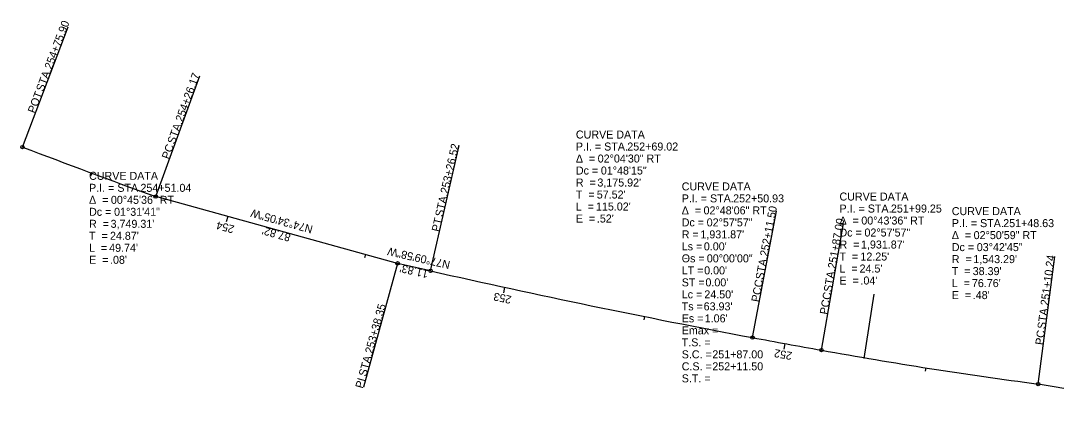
# Model space of a CAD drawing. Extents: x 2479470 to 2480226, y 287083 to 287867.
# Drawn here: x 2479470.1 to 2479832.4, y 287732.9 to 287867.3 of the extents above; entities that cross this region are included whole.
import ezdxf

# ---------------------------------------------------------------- set-up
doc = ezdxf.new("R2010")
doc.units = 0
for name, color, linetype in [('Default', 7, 'Continuous'), ('DV_X_Lot_Line', 7, 'Continuous'), ('DV_X_Property_Line', 7, 'Continuous'), ('GE_X_Alignment_100_Cardinal_Points', 7, 'Continuous'), ('GE_X_Alignment_100_Curve_Data', 7, 'Continuous'), ('GE_X_Alignment_100_Distances', 7, 'Continuous'), ('GE_X_Alignment_100_Stations', 7, 'Continuous')]:
    doc.layers.add(name, color=color, linetype=linetype)

msp = doc.modelspace()

# ---------------------------------------------------------------- linework, layer by layer
at = {"layer": 'Default'}
msp.add_line((2479765.18, 287749.01), (2479768.67, 287771.48), dxfattribs=at)
at = {"layer": 'DV_X_Lot_Line'}
for p, q in [((2479601.94, 287782.3), (2479517.29, 287805.67)), ((2479613.47, 287779.67), (2479601.94, 287782.3)), ((2479867.44, 287732.95), (2479826.02, 287740.04))]:
    msp.add_line(p, q, dxfattribs=at)
for centre, radius, start, end in [((2480801.36, 291328.24), 3749.31, 249.21177, 249.97185), ((2480314.88, 290877.17), 3175.92, 257.24096, 259.31608), ((2480084.24, 289654.69), 1931.87, 259.31608, 260.04266), ((2480026.85, 289270.21), 1543.29, 259.6733, 262.52312)]:
    msp.add_arc(centre, radius, start, end, dxfattribs=at)
at = {"layer": 'GE_X_Alignment_100_Cardinal_Points'}
for p, q in [((2479470.67, 287823.01), (2479486.64, 287865.08)), ((2479517.29, 287805.67), (2479532.7, 287847.95)), ((2479613.47, 287779.67), (2479623.47, 287823.55)), ((2479726.09, 287756.31), (2479734.43, 287800.53)), ((2479750.19, 287751.92), (2479757.97, 287796.24)), ((2479601.94, 287782.3), (2479589.97, 287738.92)), ((2479826.02, 287740.04), (2479831.88, 287784.66))]:
    msp.add_line(p, q, dxfattribs=at)
for centre in [(2479470.67, 287823.01), (2479517.29, 287805.67), (2479601.94, 287782.3), (2479613.47, 287779.67), (2479726.09, 287756.31), (2479750.19, 287751.92), (2479826.02, 287740.04)]:
    msp.add_circle(centre, 0.6, dxfattribs=at)
at = {"layer": 'GE_X_Alignment_100_Stations'}
for p, q in [((2479494.92, 287813.9), (2479494.51, 287812.78)), ((2479542.51, 287798.71), (2479541.98, 287796.78)), ((2479590.71, 287785.4), (2479590.39, 287784.24)), ((2479639.36, 287773.92), (2479638.94, 287771.97)), ((2479688.3, 287763.67), (2479688.06, 287762.5)), ((2479737.4, 287754.21), (2479737.04, 287752.24)), ((2479786.67, 287745.72), (2479786.48, 287744.54))]:
    msp.add_line(p, q, dxfattribs=at)

# ---------------------------------------------------------------- texts
at = {"layer": 'DV_X_Property_Line'}
for s, rotation, p in [('N74°34\'05"W', 164.5682, (2479572.49, 287795.41)), ('N77°09\'58"W', 167.1662, (2479620.5, 287783))]:
    msp.add_text(s, height=2.8, rotation=rotation, dxfattribs=at).set_placement(p)
at = {"layer": 'GE_X_Alignment_100_Cardinal_Points'}
for s, rotation, p in [('254+75.90', 69.2118, (2479480.88, 287850)), (' STA. ', 69.2118, (2479477.57, 287841.28)), ('254+26.17', 69.9719, (2479526.71, 287831.62)), ('POT', 69.2118, (2479475.04, 287834.62)), (' STA. ', 69.9719, (2479523.52, 287822.86)), ('PC', 69.9719, (2479521.94, 287818.54)), ('253+26.52', 77.1662, (2479619.55, 287806.51)), (' STA. ', 77.1662, (2479617.48, 287797.42)), ('252+11.50', 79.3161, (2479731.39, 287784.58)), ('PT', 77.1662, (2479616.51, 287793.18)), ('251+87.00', 80.0427, (2479755.13, 287780.26)), (' STA. ', 79.3161, (2479729.66, 287775.42)), ('251+10.24', 82.5231, (2479829.57, 287767.39)), (' STA. ', 80.0427, (2479753.52, 287771.08)), ('PCC', 79.3161, (2479728.37, 287768.58)), ('PCC', 80.0427, (2479752.32, 287764.22)), ('253+38.35', 74.5682, (2479593.13, 287750.51)), (' STA. ', 82.5231, (2479828.36, 287758.14)), ('PC', 82.5231, (2479827.76, 287753.58)), (' STA. ', 74.5682, (2479590.64, 287741.52)), ('PI', 74.5682, (2479589.76, 287738.32))]:
    msp.add_text(s, height=2.8, rotation=rotation, dxfattribs=at).set_placement(p)
at = {"layer": 'GE_X_Alignment_100_Curve_Data'}
for s, p in [('CURVE DATA', (2479664.29, 287826)), ('P.I. = STA. ', (2479664.29, 287821.8)), ('252+69.02', (2479682.28, 287821.8)), ('Δ  = ', (2479664.29, 287817.6)), ('02°04\'30" RT', (2479671.93, 287817.6)), ('CURVE DATA', (2479493.98, 287811.54)), ('Dc = ', (2479664.29, 287813.4)), ('01°48\'15"', (2479673.03, 287813.4)), ('R  = ', (2479664.29, 287809.2)), ("3,175.92'", (2479671.82, 287809.2)), ('CURVE DATA', (2479701.32, 287807.84)), ('P.I. = STA. ', (2479493.98, 287807.34)), ('254+51.04', (2479511.97, 287807.34)), ('T  = ', (2479664.29, 287805)), ("57.52'", (2479671.61, 287805)), ('CURVE DATA', (2479756.51, 287804.29)), ('Δ  = ', (2479493.98, 287803.14)), ('00°45\'36" RT', (2479501.63, 287803.14)), ('L  = ', (2479664.29, 287800.8)), ("115.02'", (2479671.32, 287800.8)), ('P.I. = STA. ', (2479701.32, 287803.64)), ('252+50.93', (2479719.31, 287803.64)), ('Dc = ', (2479493.98, 287798.94)), ('01°31\'41"', (2479502.73, 287798.94)), ('Δ  = ', (2479701.32, 287799.44)), ('02°48\'06" RT', (2479708.96, 287799.44)), ('P.I. = STA. ', (2479756.51, 287800.09)), ('251+99.25', (2479774.5, 287800.09)), ('CURVE DATA', (2479795.8, 287799.18)), ('R  = ', (2479493.98, 287794.74)), ("3,749.31'", (2479501.52, 287794.74)), ('E  = ', (2479664.29, 287796.6)), (".52'", (2479671.63, 287796.6)), ('Dc = ', (2479701.32, 287795.24)), ('02°57\'57"', (2479710.06, 287795.24)), ('Δ  = ', (2479756.51, 287795.89)), ('00°43\'36" RT', (2479764.15, 287795.89)), ('P.I. = STA. ', (2479795.8, 287794.98)), ('251+48.63', (2479813.79, 287794.98)), ('T  = ', (2479493.98, 287790.54)), ("24.87'", (2479501.3, 287790.54)), ('R = ', (2479701.32, 287791.04)), ("1,931.87'", (2479707.86, 287791.04)), ('Dc = ', (2479756.51, 287791.69)), ('02°57\'57"', (2479765.25, 287791.69)), ('Δ  = ', (2479795.8, 287790.78)), ('02°50\'59" RT', (2479803.45, 287790.78)), ('L  = ', (2479493.98, 287786.34)), ("49.74'", (2479501.02, 287786.34)), ('Ls = ', (2479701.32, 287786.84)), ("0.00'", (2479709.06, 287786.84)), ('R  = ', (2479756.51, 287787.49)), ("1,931.87'", (2479764.04, 287787.49)), ('Dc = ', (2479795.8, 287786.58)), ('03°42\'45"', (2479804.54, 287786.58)), ('Θs = ', (2479701.32, 287782.64)), ('00°00\'00"', (2479710.1, 287782.64)), ('T  = ', (2479756.51, 287783.29)), ("12.25'", (2479763.83, 287783.29)), ("1,543.29'", (2479803.33, 287782.38)), ('E  = ', (2479493.98, 287782.14)), (".08'", (2479501.32, 287782.14)), ('L  = ', (2479756.51, 287779.09)), ("24.5'", (2479763.54, 287779.09)), ('R  = ', (2479795.8, 287782.38)), ('LT = ', (2479701.32, 287778.44)), ("0.00'", (2479709.17, 287778.44)), ('T  = ', (2479795.8, 287778.18)), ("38.39'", (2479803.12, 287778.18)), ('ST = ', (2479701.32, 287774.24)), ("0.00'", (2479709.62, 287774.24)), ('E  = ', (2479756.51, 287774.89)), (".04'", (2479763.85, 287774.89)), ('L  = ', (2479795.8, 287773.98)), ("76.76'", (2479802.84, 287773.98)), ('Lc = ', (2479701.32, 287770.04)), ("24.50'", (2479709.23, 287770.04)), ('E  = ', (2479795.8, 287769.78)), (".48'", (2479803.14, 287769.78)), ('Ts = ', (2479701.32, 287765.84)), ("63.93'", (2479709, 287765.84)), ('Es = ', (2479701.32, 287761.64)), ("1.06'", (2479709.37, 287761.64)), ('Emax = ', (2479701.32, 287757.44)), ('T.S. = ', (2479701.32, 287753.24)), ('S.C. = ', (2479701.32, 287749.04)), ('251+87.00', (2479712.02, 287749.04)), ('C.S. = ', (2479701.32, 287744.84)), ('252+11.50', (2479712.02, 287744.84)), ('S.T. = ', (2479701.32, 287740.64))]:
    msp.add_text(s, height=2.8, dxfattribs=at).set_placement(p)
at = {"layer": 'GE_X_Alignment_100_Distances'}
for s, rotation, p in [("87.82'", 164.5682, (2479564.73, 287792.53)), ("11.83'", 167.1662, (2479612.89, 287779.77))]:
    msp.add_text(s, height=2.8, rotation=rotation, dxfattribs=at).set_placement(p)
at = {"layer": 'GE_X_Alignment_100_Stations'}
for s, rotation, p in [('254', 164.5682, (2479545.01, 287795.42)), ('253', 167.7194, (2479641.96, 287770.8)), ('252', 169.6571, (2479740.11, 287751.17))]:
    msp.add_text(s, height=2.8, rotation=rotation, dxfattribs=at).set_placement(p)

doc.saveas('drawing.dxf')
